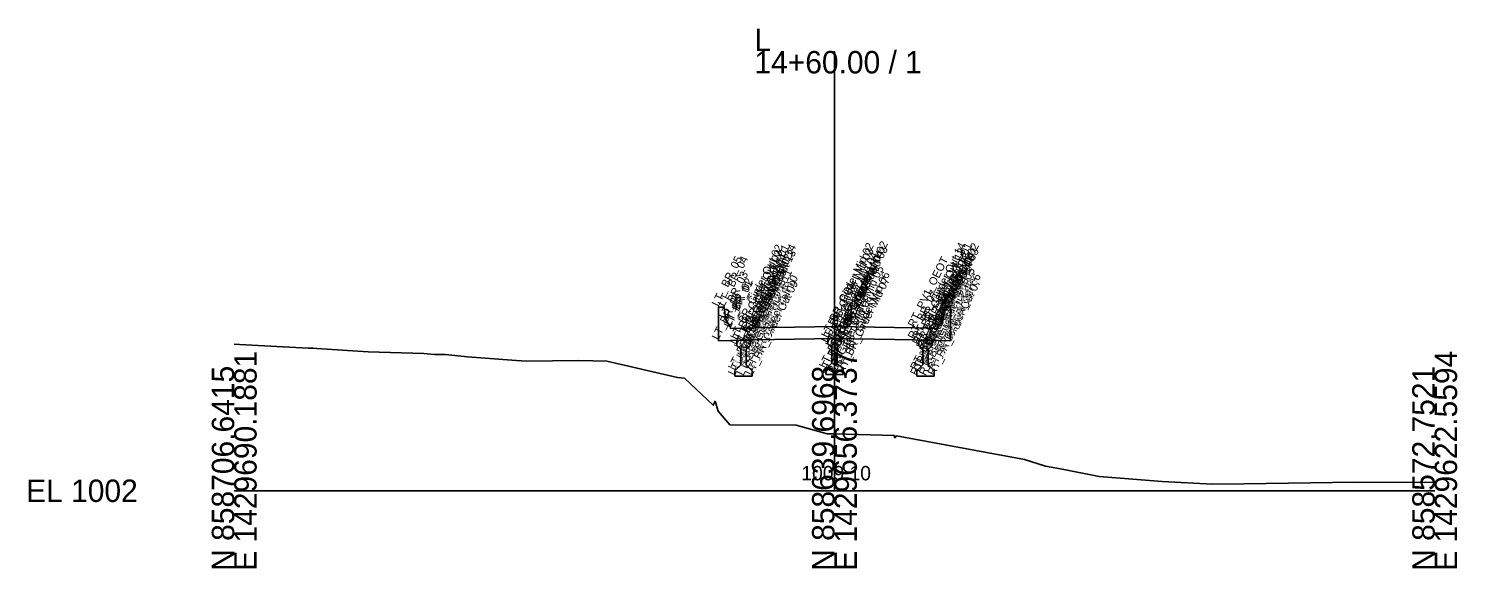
# Model space of a CAD drawing. Extents: x -26 to 2303, y -10 to 19558.
# Drawn here: x 1124.3 to 1302.8, y 18990.3 to 19057.7 of the extents above; entities that cross this region are included whole.
import ezdxf

# ---------------------------------------------------------------- set-up
doc = ezdxf.new("R2010")
doc.units = 0
for name, color, linetype in [('Default', 7, 'Continuous'), ('Exist Cross Section Cell', 7, 'Continuous'), ('Exist XS Center Line Elevation Label', 7, 'Continuous'), ('Exist XS Ground Line', 7, 'Continuous'), ('Prop CMT Concrete Structures', 7, 'Continuous'), ('Prop XS Dump Level', 7, 'Continuous')]:
    doc.layers.add(name, color=color, linetype=linetype)

msp = doc.modelspace()

# ---------------------------------------------------------------- linework, layer by layer
at = {"layer": 'Exist Cross Section Cell'}
for p, q in [((1225, 19000), (1225, 19054.91)), ((1150, 19000), (1225, 19000)), ((1225, 19000), (1300, 19000))]:
    msp.add_line(p, q, dxfattribs=at)
at = {"layer": 'Exist XS Ground Line'}
msp.add_lwpolyline([(1150, 19018.3), (1150.67, 19018.25), (1159.24, 19017.82), (1159.84, 19017.79), (1160.31, 19017.77), (1166.73, 19017.33), (1173.69, 19017.15), (1175.04, 19017.01), (1176.39, 19017.01), (1179.13, 19016.74), (1184.69, 19016.32), (1186.5, 19016.2), (1193.07, 19016.28), (1196.56, 19016.18), (1205.37, 19014.15), (1206.27, 19014.06), (1209.86, 19010.67), (1210.09, 19011.18), (1210.48, 19009.94), (1211.93, 19008.25), (1220.2, 19008.21), (1224.07, 19007.12), (1225, 19007.1), (1232.48, 19006.89), (1232.55, 19006.62), (1232.75, 19006.85), (1248.75, 19003.91), (1251.38, 19003.07), (1253.26, 19002.73), (1258.09, 19001.78), (1265.95, 19001.17), (1272.25, 19000.83), (1276.18, 19000.85), (1289.99, 19001.06), (1300, 19001.02)], dxfattribs=at)
at = {"layer": 'Prop CMT Concrete Structures'}
for points in [[(1225, 19020.53), (1215, 19020.33), (1212, 19020.27), (1211.99, 19020.52), (1211.41, 19021.35), (1211.24, 19022.93), (1210.5, 19022.93), (1210.5, 19018.74)], [(1225, 19020.53), (1235, 19020.33), (1238, 19020.27), (1238.01, 19020.52), (1238.59, 19021.35), (1238.76, 19022.93), (1239.5, 19022.93), (1239.5, 19018.74)], [(1225, 19019.03), (1225, 19020.53)], [(1225, 19019.03), (1225, 19020.53)], [(1210.5, 19018.74), (1215, 19018.83), (1225, 19019.03)], [(1214.46, 19018.82), (1213.62, 19018.8), (1212.79, 19018.78)], [(1212.79, 19018.78), (1212.79, 19018.13)], [(1212.79, 19018.13), (1213.29, 19017.63)], [(1213.29, 19017.63), (1213.29, 19015.72)], [(1213.96, 19017.63), (1214.46, 19018.13)], [(1213.96, 19015.72), (1213.96, 19017.63)], [(1214.46, 19018.13), (1214.46, 19018.82)], [(1225, 19019.03), (1224.17, 19019.01)], [(1224.17, 19019.01), (1224.17, 19018.36)], [(1224.17, 19018.36), (1224.67, 19017.86)], [(1224.67, 19017.86), (1224.67, 19015.94)], [(1225, 19014.53), (1225, 19019.03)], [(1225, 19019.03), (1225.83, 19019.01)], [(1225, 19014.53), (1225, 19019.03)], [(1239.5, 19018.74), (1235, 19018.83), (1225, 19019.03)], [(1225.83, 19018.36), (1225.33, 19017.86)], [(1225.33, 19017.86), (1225.33, 19015.94)], [(1225.83, 19019.01), (1225.83, 19018.36)], [(1235.54, 19018.82), (1236.38, 19018.8), (1237.21, 19018.78)], [(1235.54, 19018.13), (1235.54, 19018.82)], [(1236.04, 19017.63), (1235.54, 19018.13)], [(1236.04, 19015.72), (1236.04, 19017.63)], [(1237.21, 19018.13), (1236.71, 19017.63)], [(1236.71, 19017.63), (1236.71, 19015.72)], [(1237.21, 19018.78), (1237.21, 19018.13)], [(1213.29, 19015.72), (1212.54, 19014.97)], [(1214.71, 19014.97), (1213.96, 19015.72)], [(1224.67, 19015.94), (1223.92, 19015.19)], [(1225.33, 19015.94), (1226.08, 19015.19)], [(1235.29, 19014.97), (1236.04, 19015.72)], [(1236.71, 19015.72), (1237.46, 19014.97)], [(1212.54, 19014.97), (1212.54, 19014.3)], [(1212.54, 19014.3), (1213.62, 19014.3), (1214.71, 19014.3)], [(1214.71, 19014.3), (1214.71, 19014.97)], [(1223.92, 19015.19), (1223.92, 19014.53)], [(1223.92, 19014.53), (1225, 19014.53)], [(1226.08, 19014.53), (1225, 19014.53)], [(1226.08, 19015.19), (1226.08, 19014.53)], [(1235.29, 19014.3), (1235.29, 19014.97)], [(1237.46, 19014.3), (1236.38, 19014.3), (1235.29, 19014.3)], [(1237.46, 19014.97), (1237.46, 19014.3)]]:
    msp.add_lwpolyline(points, dxfattribs=at)

# ---------------------------------------------------------------- texts
at = {"layer": 'Default'}
msp.add_text('-', height=0.0001, dxfattribs=at).set_placement((1150, 19000))
at = {"layer": 'Exist Cross Section Cell'}
for s, p in [('L', (1215, 19054.91)), ('14+60.00 / 1', (1215, 19052.11)), ('EL 1002', (1124, 18998.6))]:
    msp.add_text(s, height=2.8, dxfattribs=at).set_placement(p)
for s, p in [('E 1429690.1881', (1152.8, 18990)), ('E 1429656.3737', (1227.8, 18990)), ('E 1429622.5594', (1302.8, 18990)), ('N 858706.6415', (1150, 18990)), ('N 858639.6968', (1225, 18990)), ('N 858572.7521', (1300, 18990))]:
    msp.add_text(s, height=2.8, rotation=90, dxfattribs=at).set_placement(p)
at = {"layer": 'Exist XS Center Line Elevation Label'}
msp.add_text('1009.10', height=1.8, dxfattribs=at).set_placement((1220.86, 19001.3))
at = {"layer": 'Prop XS Dump Level'}
for s, p in [('LT_BR_Girder Out 02', (1212.79, 19018.78)), ('LT_BR_Girder Out 03', (1212.79, 19018.13)), ('LT_BR_Girder Out 01', (1213.62, 19018.8)), ('LT_BR_Girder Out 14', (1214.46, 19018.82)), ('LT_BR_Girder Out 13', (1214.46, 19018.13)), ('LT_BR_Girder Mid 02', (1224.17, 19019.01)), ('LT_BR_Girder Mid 03', (1224.17, 19018.36)), ('LT_BR_Girder Mid 04', (1224.67, 19017.86)), ('RT_BR_Girder Mid 04', (1225.33, 19017.86)), ('RT_BR_Girder Mid 02', (1225.83, 19019.01)), ('RT_BR_Girder Mid 03', (1225.83, 19018.36)), ('RT_BR_Girder Out 14', (1235.54, 19018.82)), ('RT_BR_Girder Out 13', (1235.54, 19018.13)), ('RT_BR_Girder Out 12', (1236.04, 19017.63)), ('RT_BR_Girder Out 01', (1236.38, 19018.8)), ('RT_BR_Girder Out 02', (1237.21, 19018.78)), ('RT_BR_Girder Out 03', (1237.21, 19018.13)), ('LT_ BR_05', (1210.5, 19022.93)), ('LT_ BR_04', (1211.24, 19022.93)), ('LT_BR_Girder Out 04', (1213.29, 19017.63)), ('LT_BR_Girder Out 12', (1213.96, 19017.63)), ('LT_PV1_OEOT', (1215, 19020.33)), ('RT_BR_Girder Mid 05', (1225.33, 19015.94)), ('RT_PV1_OEOT', (1235, 19020.33)), ('RT_BR_Girder Out 04', (1236.71, 19017.63)), ('RT_ BR_04', (1238.76, 19022.93)), ('RT_ BR_05', (1239.5, 19022.93)), ('LT_BR_03', (1211.41, 19021.35)), ('LT_BR_02', (1211.99, 19020.52)), ('LT_BR_Girder Out 06', (1212.54, 19014.97)), ('LT_BR_Girder Out 07', (1212.54, 19014.3)), ('LT_BR_Girder Out 05', (1213.29, 19015.72)), ('LT_BR_Girder Out 08', (1213.62, 19014.3)), ('LT_BR_Girder Out 11', (1213.96, 19015.72)), ('LT_BR_Girder Out 10', (1214.71, 19014.97)), ('LT_BR_Girder Out 09', (1214.71, 19014.3)), ('LT_BR_Girder Mid 06', (1223.92, 19015.19)), ('LT_BR_Girder Mid 07', (1223.92, 19014.53)), ('LT_BR_Girder Mid 05', (1224.67, 19015.94)), ('RT_BR_Girder Mid 06', (1226.08, 19015.19)), ('RT_BR_Girder Mid 07', (1226.08, 19014.53)), ('RT_BR_Girder Out 10', (1235.29, 19014.97)), ('RT_BR_Girder Out 09', (1235.29, 19014.3)), ('RT_BR_Girder Out 11', (1236.04, 19015.72)), ('RT_BR_Girder Out 08', (1236.38, 19014.3)), ('RT_BR_Girder Out 05', (1236.71, 19015.72)), ('RT_BR_Girder Out 06', (1237.46, 19014.97)), ('RT_BR_Girder Out 07', (1237.46, 19014.3)), ('RT_BR_01', (1238, 19020.27)), ('RT_BR_02', (1238.01, 19020.52)), ('RT_BR_03', (1238.59, 19021.35)), ('LT_BR_06', (1210.5, 19018.74)), ('LT_BR_01', (1212, 19020.27)), ('LT_BR_07', (1215, 19018.83)), ('PV1_PGL', (1225, 19020.53)), ('RT_BR_07', (1235, 19018.83)), ('RT_BR_06', (1239.5, 19018.74)), ('BR_Girder Mid 08', (1225, 19014.53)), ('BR_PGL', (1225, 19019.03))]:
    msp.add_text(s, height=1, rotation=63.5833, dxfattribs=at).set_placement(p)

doc.saveas('drawing.dxf')
